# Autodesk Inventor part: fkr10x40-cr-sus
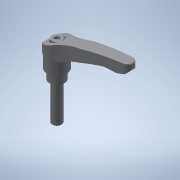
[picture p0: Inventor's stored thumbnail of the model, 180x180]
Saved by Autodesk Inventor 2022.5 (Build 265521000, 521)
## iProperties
Created: 2017-09
Part Number: fkr10x40-cr-sus
Material: 一般
Document SubType Name: Modeling
Designer: imaocorp
Density: 1 g/cm^3
Appearance: 既定
Author: imaocorp
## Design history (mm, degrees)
node "fkr10x40-cr-sus.x_t1"
node "fkr10x40-cr-sus"
node "Base1"
